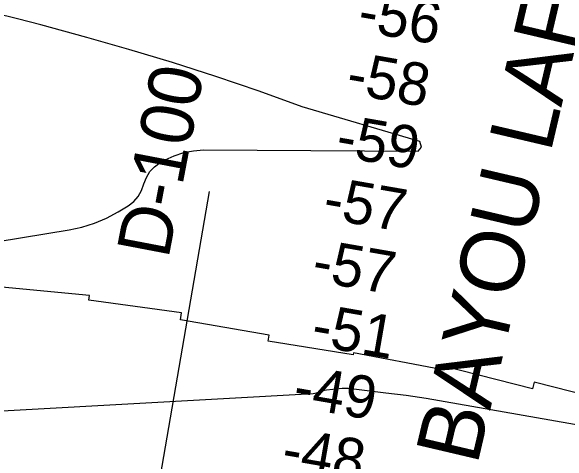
# Model space of a CAD drawing. Extents: x 3361039 to 3398939, y 576572 to 602007.
# Drawn here: x 3388488 to 3389365, y 585794 to 586504 of the extents above; entities that cross this region are included whole.
import ezdxf

# ---------------------------------------------------------------- set-up
doc = ezdxf.new("R2010")
doc.units = 0
for name, color, linetype in [('V-CHAN-NAID', 7, 'Continuous'), ('V-RIVR-RANG', 7, 'Continuous'), ('V-RIVR-RANG-IDEN', 7, 'Continuous'), ('V-RRAP-RVMT', 7, 'Continuous'), ('V-TOPO-MAJR', 7, 'Continuous'), ('V-TOPO-MINR', 7, 'Continuous')]:
    doc.layers.add(name, color=color, linetype=linetype)

msp = doc.modelspace()

# ---------------------------------------------------------------- linework, layer by layer
at = {"layer": 'V-RIVR-RANG'}
msp.add_line((3388640.33, 585293.62), (3388800.52, 586219.88), dxfattribs=at)
at = {"layer": 'V-RRAP-RVMT'}
msp.add_lwpolyline([(3389654.54, 585812.59), (3389567.1, 585833.81), (3389570.66, 585848.13), (3389461.12, 585875.39), (3389462.62, 585881.31), (3389311.7, 585919.54), (3389309.04, 585908.91), (3389166.85, 585945.51), (3389165.33, 585939.66), (3389027.22, 585965.92), (3389026.61, 585962.63), (3388892.79, 585983.98), (3388894.45, 585993.62), (3388754.69, 586017.77), (3388756.31, 586028.63), (3388610.61, 586048.84), (3388611.3, 586055.94), (3388473.17, 586069.24)], dxfattribs=at)
at = {"layer": 'V-TOPO-MAJR'}
msp.add_lwpolyline([(3388219.26, 585860.42), (3388963.59, 585901.55), (3388966.23, 585902.2), (3388968.85, 585902.94), (3388971.43, 585903.8), (3388973.99, 585904.73), (3388976.55, 585905.62), (3388979.15, 585906.38), (3388981.8, 585906.94), (3388984.48, 585907.36), (3389004.48, 585909.73), (3389009.22, 585910.11), (3389013.97, 585910.27), (3389018.71, 585910.09), (3389023.45, 585909.68), (3389078.01, 585902.99), (3389110, 585898.82), (3389141.94, 585894.31), (3389612.25, 585812.11)], dxfattribs=at)
at = {"layer": 'V-TOPO-MINR'}
msp.add_lwpolyline([(3388352.18, 586122.23), (3388579.42, 586159.36), (3388599.61, 586163.85), (3388619.26, 586169.82), (3388638.11, 586177.98), (3388656.42, 586187.61), (3388672.37, 586197.2), (3388681.07, 586204.05), (3388688.34, 586211.92), (3388693.49, 586221.32), (3388697.21, 586231.74), (3388700.99, 586242.08), (3388706.24, 586251.31), (3388713.69, 586258.87), (3388722.6, 586265.33), (3388730.57, 586269.62), (3388745.06, 586276.13), (3388759.91, 586281.19), (3388775.34, 586284.08), (3388791.15, 586285.54), (3389129.01, 586283.21), (3389134.38, 586289.43), (3389131.73, 586298.35), (3388946.39, 586353.23), (3388878.7, 586377.63), (3388810.66, 586400.97), (3388742.09, 586422.73), (3388673.18, 586443.44), (3388607.44, 586462.36), (3388571.07, 586472.54), (3388534.59, 586482.33), (3388497.97, 586491.57), (3388461.26, 586500.44)], dxfattribs=at)

# ---------------------------------------------------------------- texts
at = {"layer": 'V-CHAN-NAID'}
msp.add_text('BAYOU LAFOURCHE INTAKE (175.4) (2)', height=100, rotation=76.78368, dxfattribs=at).set_placement((3389221.84, 585787.16))
at = {"layer": 'V-RIVR-RANG'}
for s, p in [('-56', (3389031.45, 586473.1)), ('-58', (3389013.57, 586374.7)), ('-59', (3388996.99, 586276.09)), ('-57', (3388976.78, 586178.1)), ('-57', (3388959.43, 586079.62)), ('-51', (3388958.44, 585978.29)), ('-49', (3388929.65, 585881.8)), ('-48', (3388911.52, 585783.45))]:
    msp.add_text(s, height=67, rotation=350.14722, dxfattribs=at).set_placement(p)
at = {"layer": 'V-RIVR-RANG-IDEN'}
msp.add_text('D-100', height=83, rotation=79.18146, dxfattribs=at).set_placement((3388735.56, 586112.28))

doc.saveas('drawing.dxf')
